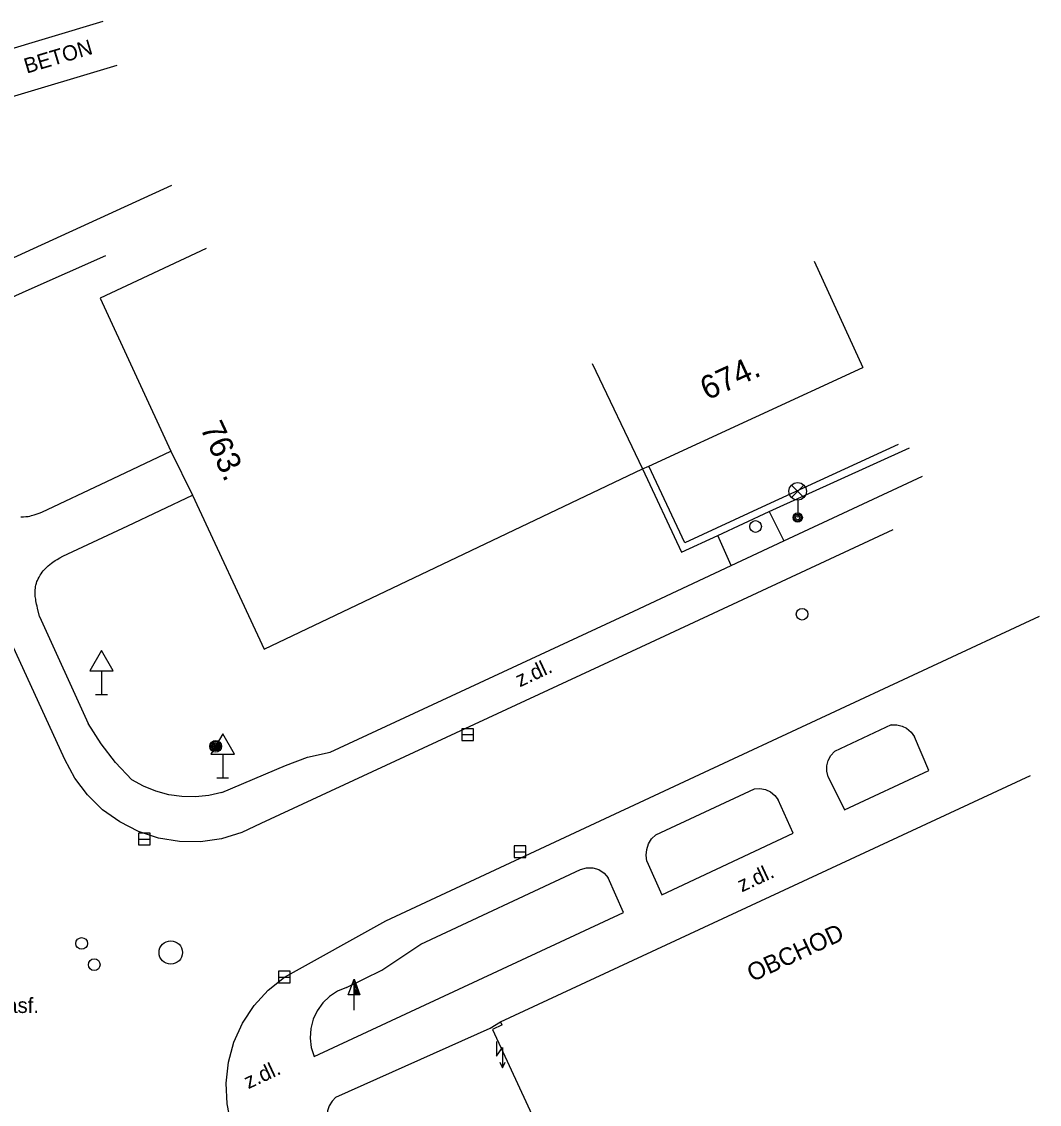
# Model space of a CAD drawing. Extents: x -539515 to -538098, y -1182060 to -1180157.
# Drawn here: x -538279.17 to -538235.67, y -1181255.02 to -1181208.72 of the extents above; entities that cross this region are included whole.
import ezdxf

# ---------------------------------------------------------------- set-up
doc = ezdxf.new("R2010")
doc.units = 0
for name, color, linetype in [('Vrstva 1', 7, 'Continuous'), ('Vrstva 13', 7, 'Continuous'), ('Vrstva 24', 7, 'Continuous'), ('Vrstva 25', 7, 'Continuous'), ('Vrstva 27', 7, 'Continuous'), ('Vrstva 28', 7, 'Continuous'), ('Vrstva 33', 7, 'Continuous'), ('Vrstva 34', 7, 'Continuous'), ('Vrstva 40', 7, 'Continuous'), ('Vrstva 41', 7, 'Continuous'), ('Vrstva 47', 7, 'Continuous'), ('Vrstva 68', 7, 'Continuous'), ('Vrstva 88', 7, 'Continuous')]:
    doc.layers.add(name, color=color, linetype=linetype)

msp = doc.modelspace()

# ---------------------------------------------------------------- linework, layer by layer
at = {"layer": 'Vrstva 1'}
for p, q in [((-538275.709, -1181208.719), (-538280.5, -1181210.15)), ((-538271.28, -1181218.424), (-538275.81, -1181220.54)), ((-538245.3, -1181218.968), (-538243.21, -1181223.51)), ((-538254.791, -1181223.336), (-538252.64, -1181227.85)), ((-538268.8, -1181235.55), (-538252.64, -1181227.85)), ((-538258.7, -1181251.49), (-538236.05, -1181240.96)), ((-538258.636, -1181251.628), (-538259.05, -1181251.82)), ((-538258.636, -1181251.628), (-538258.7, -1181251.49))]:
    msp.add_line(p, q, dxfattribs=at)
for points in [[(-538275.81, -1181220.54), (-538272.79, -1181227.09)], [(-538252.368, -1181227.723), (-538243.21, -1181223.51)], [(-538272.79, -1181227.09), (-538271.872, -1181228.972)], [(-538252.64, -1181227.85), (-538252.368, -1181227.723)], [(-538271.872, -1181228.972), (-538268.8, -1181235.55)], [(-538259.05, -1181251.82), (-538255.758, -1181258.936)]]:
    msp.add_lwpolyline(points, dxfattribs=at)
at = {"layer": 'Vrstva 13'}
for p, q in [((-538275.109, -1181210.599), (-538279.9, -1181212.03)), ((-538272.774, -1181215.727), (-538284.35, -1181221.03)), ((-538275.534, -1181228.382), (-538272.79, -1181227.09)), ((-538246.59, -1181230.929), (-538240.664, -1181228.155)), ((-538278.41, -1181234.16), (-538276.33, -1181238.74)), ((-538265.98, -1181239.96), (-538253, -1181233.93)), ((-538242, -1181238.79), (-538244.43, -1181239.93)), ((-538252.07, -1181243.49), (-538247.85, -1181241.53)), ((-538246.19, -1181243.42), (-538246.84, -1181242)), ((-538251.81, -1181246.06), (-538246.19, -1181243.42)), ((-538252.45, -1181244.62), (-538251.81, -1181246.06)), ((-538262.11, -1181248.17), (-538255.28, -1181244.98)), ((-538253.45, -1181246.82), (-538254.1, -1181245.34)), ((-538260.49, -1181250.1), (-538253.45, -1181246.82)), ((-538266.67, -1181252.98), (-538260.49, -1181250.1)), ((-538265.74, -1181254.72), (-538259.14, -1181251.76)), ((-538259.14, -1181251.76), (-538258.7, -1181251.49))]:
    msp.add_line(p, q, dxfattribs=at)
for points in [[(-538275.59, -1181218.74), (-538278.865, -1181220.195), (-538282.14, -1181221.65)], [(-538278.31, -1181229.69), (-538275.534, -1181228.382)], [(-538278.12, -1181232.071), (-538278.041, -1181231.996), (-538277.969, -1181231.934), (-538277.904, -1181231.881), (-538277.846, -1181231.837), (-538277.741, -1181231.765), (-538277.661, -1181231.714), (-538277.537, -1181231.644), (-538277.41, -1181231.58), (-538274.641, -1181230.276), (-538271.872, -1181228.972)], [(-538279.207, -1181229.903), (-538279.09, -1181229.898), (-538278.989, -1181229.888), (-538278.9, -1181229.875), (-538278.823, -1181229.861), (-538278.756, -1181229.846), (-538278.64, -1181229.815), (-538278.555, -1181229.788), (-538278.43, -1181229.742), (-538278.31, -1181229.69)], [(-538247.22, -1181229.67), (-538246.59, -1181230.929)], [(-538253, -1181233.93), (-538248.842, -1181231.983), (-538246.59, -1181230.929)], [(-538248.842, -1181231.983), (-538249.42, -1181230.691)], [(-538278.41, -1181234.16), (-538278.489, -1181233.802), (-538278.513, -1181233.718), (-538278.533, -1181233.637), (-538278.55, -1181233.562), (-538278.564, -1181233.491), (-538278.574, -1181233.424), (-538278.589, -1181233.298), (-538278.596, -1181233.189), (-538278.596, -1181233.094), (-538278.592, -1181233.012), (-538278.585, -1181232.94), (-538278.576, -1181232.878), (-538278.565, -1181232.825), (-538278.542, -1181232.733), (-538278.521, -1181232.665), (-538278.502, -1181232.615), (-538278.469, -1181232.541), (-538278.43, -1181232.47), (-538278.384, -1181232.396), (-538278.338, -1181232.329), (-538278.293, -1181232.268), (-538278.249, -1181232.212), (-538278.205, -1181232.162), (-538278.12, -1181232.071)], [(-538274.47, -1181241.15), (-538275.161, -1181240.402), (-538275.78, -1181239.598), (-538276.33, -1181238.74)], [(-538242, -1181238.79), (-538241.764, -1181238.791), (-538241.536, -1181238.848), (-538241.35, -1181238.94), (-538241.148, -1181239.109), (-538241.01, -1181239.3)], [(-538244.7, -1181241.01), (-538244, -1181242.43), (-538240.39, -1181240.74), (-538241.01, -1181239.3)], [(-538270.62, -1181241.69), (-538267.9, -1181240.53), (-538266.96, -1181240.18), (-538265.98, -1181239.96)], [(-538244.7, -1181241.01), (-538244.752, -1181240.78), (-538244.749, -1181240.545), (-538244.692, -1181240.317), (-538244.584, -1181240.108), (-538244.43, -1181239.93)], [(-538270.62, -1181241.69), (-538271.178, -1181241.814), (-538271.748, -1181241.871), (-538272.32, -1181241.859), (-538272.886, -1181241.78), (-538273.439, -1181241.633), (-538273.971, -1181241.421), (-538274.47, -1181241.15)], [(-538247.85, -1181241.53), (-538247.613, -1181241.514), (-538247.379, -1181241.558), (-538247.164, -1181241.658), (-538246.98, -1181241.808), (-538246.84, -1181242)], [(-538252.45, -1181244.62), (-538252.48, -1181244.371), (-538252.454, -1181244.122), (-538252.374, -1181243.884), (-538252.244, -1181243.67), (-538252.07, -1181243.49)], [(-538255.28, -1181244.98), (-538255.022, -1181244.905), (-538254.753, -1181244.906), (-538254.496, -1181244.985), (-538254.272, -1181245.134), (-538254.1, -1181245.34)], [(-538265.29, -1181250.03), (-538263.78, -1181249.28), (-538262.11, -1181248.17)], [(-538265.29, -1181250.03), (-538265.667, -1181250.184), (-538266.01, -1181250.405), (-538266.305, -1181250.686), (-538266.543, -1181251.017), (-538266.716, -1181251.386), (-538266.817, -1181251.781), (-538266.843, -1181252.187), (-538266.794, -1181252.592), (-538266.67, -1181252.98)], [(-538265.74, -1181254.72), (-538265.905, -1181254.883), (-538266.025, -1181255.081), (-538266.095, -1181255.303), (-538266.108, -1181255.534), (-538266.11, -1181255.8)]]:
    msp.add_lwpolyline(points, dxfattribs=at)
at = {"layer": 'Vrstva 24'}
for p, q in [((-538258.87, -1181252.334), (-538258.87, -1181252.96)), ((-538258.87, -1181252.96), (-538258.62, -1181252.585)), ((-538258.62, -1181252.585), (-538258.62, -1181253.46)), ((-538258.73, -1181253.215), (-538258.62, -1181253.46)), ((-538258.62, -1181253.46), (-538258.51, -1181253.215))]:
    msp.add_line(p, q, dxfattribs=at)
at = {"layer": 'Vrstva 25'}
for p, q in [((-538265.213, -1181250.338), (-538264.96, -1181249.664)), ((-538264.96, -1181250.338), (-538265.213, -1181250.338)), ((-538264.96, -1181250.99), (-538264.96, -1181250.34))]:
    msp.add_line(p, q, dxfattribs=at)
for points in [[(-538264.71, -1181250.34), (-538264.96, -1181250.34), (-538264.96, -1181249.664), (-538264.96, -1181249.664)], [(-538264.768, -1181250.3), (-538264.921, -1181250.3), (-538264.921, -1181249.888)], [(-538264.825, -1181250.261), (-538264.881, -1181250.261), (-538264.881, -1181250.111)]]:
    msp.add_lwpolyline(points, close=True, dxfattribs=at)
for radius in [0.25, 0.2, 0.15, 0.1, 0.05]:
    msp.add_circle((-538270.88, -1181239.71), radius, dxfattribs=at)
at = {"layer": 'Vrstva 27'}
for p, q in [((-538260.36, -1181239.21), (-538259.86, -1181239.21)), ((-538274.18, -1181243.68), (-538273.68, -1181243.68)), ((-538258.12, -1181244.22), (-538257.62, -1181244.22)), ((-538268.19, -1181249.58), (-538267.69, -1181249.58))]:
    msp.add_line(p, q, dxfattribs=at)
for points in [[(-538260.36, -1181239.46), (-538259.86, -1181239.46), (-538259.86, -1181238.96), (-538260.36, -1181238.96)], [(-538274.18, -1181243.93), (-538273.68, -1181243.93), (-538273.68, -1181243.43), (-538274.18, -1181243.43)], [(-538258.12, -1181244.47), (-538257.62, -1181244.47), (-538257.62, -1181243.97), (-538258.12, -1181243.97)], [(-538268.19, -1181249.83), (-538267.69, -1181249.83), (-538267.69, -1181249.33), (-538268.19, -1181249.33)]]:
    msp.add_lwpolyline(points, close=True, dxfattribs=at)
msp.add_circle((-538272.8, -1181248.53), 0.5, dxfattribs=at)
at = {"layer": 'Vrstva 28'}
for centre in [(-538247.8, -1181230.31), (-538245.81, -1181234.06), (-538276.61, -1181248.14), (-538276.07, -1181249.05)]:
    msp.add_circle(centre, 0.25, dxfattribs=at)
at = {"layer": 'Vrstva 33'}
for p, q in [((-538246.265, -1181229.07), (-538245.735, -1181228.54)), ((-538246.265, -1181228.54), (-538245.735, -1181229.07)), ((-538246, -1181229.18), (-538246, -1181229.93))]:
    msp.add_line(p, q, dxfattribs=at)
for centre, radius in [((-538246, -1181228.805), 0.375), ((-538246, -1181229.93), 0.2), ((-538246, -1181229.93), 0.145), ((-538246, -1181229.93), 0.0876)]:
    msp.add_circle(centre, radius, dxfattribs=at)
at = {"layer": 'Vrstva 34'}
for p, q in [((-538275.76, -1181236.482), (-538275.76, -1181237.5)), ((-538276.01, -1181237.5), (-538275.51, -1181237.5)), ((-538270.58, -1181240.044), (-538270.58, -1181241.06)), ((-538270.83, -1181241.06), (-538270.33, -1181241.06))]:
    msp.add_line(p, q, dxfattribs=at)
for points in [[(-538276.26, -1181236.482), (-538275.26, -1181236.482), (-538275.76, -1181235.616)], [(-538271.08, -1181240.044), (-538270.08, -1181240.044), (-538270.58, -1181239.176)]]:
    msp.add_lwpolyline(points, close=True, dxfattribs=at)
at = {"layer": 'Vrstva 68'}
for points in [[(-538241.698, -1181226.796), (-538247.346, -1181229.398)], [(-538247.22, -1181229.67), (-538241.22, -1181226.95)], [(-538247.346, -1181229.398), (-538250.825, -1181231.012), (-538252.368, -1181227.723)], [(-538252.64, -1181227.85), (-538250.97, -1181231.41), (-538249.42, -1181230.691), (-538247.22, -1181229.67)]]:
    msp.add_lwpolyline(points, dxfattribs=at)
at = {"layer": 'Vrstva 88'}
for p, q in [((-538241.93, -1181230.45), (-538252.31, -1181235.28)), ((-538249.98, -1181240.82), (-538235.67, -1181234.14)), ((-538277.33, -1181240.27), (-538279.9, -1181234.65)), ((-538252.31, -1181235.28), (-538268.95, -1181243.01)), ((-538263.61, -1181247.18), (-538249.98, -1181240.82)), ((-538267.94, -1181249.58), (-538263.61, -1181247.18))]:
    msp.add_line(p, q, dxfattribs=at)
for points in [[(-538268.95, -1181243.01), (-538269.764, -1181243.401), (-538270.629, -1181243.664), (-538271.523, -1181243.793), (-538272.427, -1181243.783), (-538273.318, -1181243.636), (-538274.177, -1181243.356), (-538274.983, -1181242.947), (-538275.718, -1181242.421), (-538276.364, -1181241.79), (-538276.906, -1181241.067), (-538277.33, -1181240.27)], [(-538269.9, -1181256.72), (-538270.215, -1181255.88), (-538270.395, -1181255.004), (-538270.435, -1181254.111), (-538270.335, -1181253.222), (-538270.098, -1181252.36), (-538269.728, -1181251.546), (-538269.236, -1181250.8), (-538268.634, -1181250.139), (-538267.94, -1181249.58)]]:
    msp.add_lwpolyline(points, dxfattribs=at)

# ---------------------------------------------------------------- texts
at = {"layer": 'Vrstva 40'}
for s, rotation, p in [('BETON', 16.6301, (-538278.958, -1181210.945)), ('z.dl.', 25.0019, (-538257.877, -1181237.192)), ('z.dl.', 25.0019, (-538248.391, -1181245.962)), ('z.dl.', 25.0019, (-538269.485, -1181254.378))]:
    msp.add_text(s, height=0.65, rotation=rotation, dxfattribs=at).set_placement(p)
msp.add_text('asf.', height=0.65, dxfattribs=at).set_placement((-538279.833, -1181251.115))
at = {"layer": 'Vrstva 41'}
msp.add_text('OBCHOD', height=0.75, rotation=24.9337, dxfattribs=at).set_placement((-538247.943, -1181249.798))
at = {"layer": 'Vrstva 47'}
for s, rotation, p in [('674.', 24.7135, (-538249.871, -1181224.924)), ('763.', 295.0336, (-538271.56, -1181226.094))]:
    msp.add_text(s, height=1, rotation=rotation, dxfattribs=at).set_placement(p)

doc.saveas('drawing.dxf')
